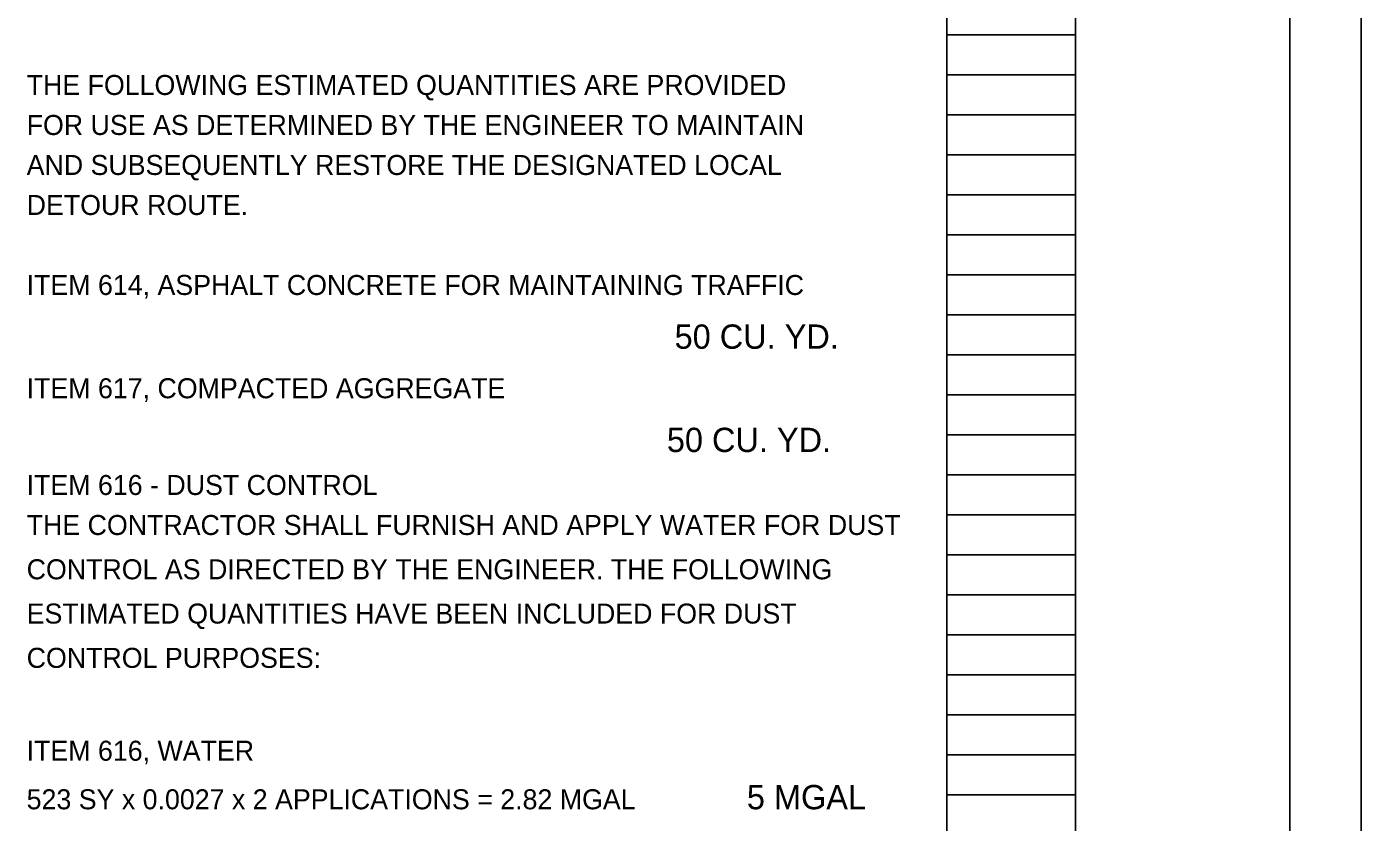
# Model space of a CAD drawing. Extents: x -59.3 to 34, y -1.2 to 22.
# Drawn here: x 24.66 to 34, y 5.55 to 11.12 of the extents above; entities that cross this region are included whole.
import ezdxf

# ---------------------------------------------------------------- set-up
doc = ezdxf.new("R2010")
doc.units = 0
for name, color, linetype in [('RD_P_Text', 7, 'Continuous'), ('SH_Border', 7, 'Continuous'), ('SH_Cut_Line', 7, 'Continuous'), ('SH_Data', 7, 'Continuous')]:
    doc.layers.add(name, color=color, linetype=linetype)

msp = doc.modelspace()

# ---------------------------------------------------------------- linework, layer by layer
at = {"layer": 'RD_P_Text'}
for p, q in [((31.1, 0.98), (31.1, 21.14)), ((32, 0.98), (32, 21.14)), ((31.1, 11.06), (32, 11.06)), ((31.1, 10.78), (32, 10.78)), ((31.1, 10.5), (32, 10.5)), ((31.1, 10.22), (32, 10.22)), ((31.1, 9.94), (32, 9.94)), ((31.1, 9.66), (32, 9.66)), ((31.1, 9.38), (32, 9.38)), ((31.1, 9.1), (32, 9.1)), ((31.1, 8.82), (32, 8.82)), ((31.1, 8.54), (32, 8.54)), ((31.1, 8.26), (32, 8.26)), ((31.1, 7.98), (32, 7.98)), ((31.1, 7.7), (32, 7.7)), ((31.1, 7.42), (32, 7.42)), ((31.1, 7.14), (32, 7.14)), ((31.1, 6.86), (32, 6.86)), ((31.1, 6.58), (32, 6.58)), ((31.1, 6.3), (32, 6.3)), ((31.1, 6.02), (32, 6.02)), ((31.1, 5.74), (32, 5.74))]:
    msp.add_line(p, q, dxfattribs=at)
at = {"layer": 'SH_Border'}
msp.add_line((32, 0.5), (32, 21.5), dxfattribs=at)
msp.add_lwpolyline([(1.5, 21.5), (33.5, 21.5), (33.5, 0.5), (1.5, 0.5)], close=True, dxfattribs=at)
at = {"layer": 'SH_Cut_Line'}
msp.add_lwpolyline([(0, 0), (34, 0), (34, 22), (0, 22)], close=True, dxfattribs=at)

# ---------------------------------------------------------------- texts
at = {"layer": 'SH_Data'}
for s, height, p in [('THE FOLLOWING ESTIMATED QUANTITIES ARE PROVIDED ', 0.14, (24.66, 10.64)), ('FOR USE AS DETERMINED BY THE ENGINEER TO MAINTAIN ', 0.14, (24.66, 10.36)), ('AND SUBSEQUENTLY RESTORE THE DESIGNATED LOCAL ', 0.14, (24.66, 10.08)), ('DETOUR ROUTE.', 0.14, (24.66, 9.8)), ('ITEM 614, ASPHALT CONCRETE FOR MAINTAINING TRAFFIC', 0.14, (24.66, 9.24)), ('50 CU. YD.', 0.17, (29.1943, 8.8636)), ('ITEM 617, COMPACTED AGGREGATE ', 0.14, (24.66, 8.5171)), ('50 CU. YD.', 0.17, (29.14, 8.1407)), ('ITEM 616 - DUST CONTROL', 0.14, (24.66, 7.84)), ('THE CONTRACTOR SHALL FURNISH AND APPLY WATER FOR DUST ', 0.14, (24.66, 7.56)), ('CONTROL AS DIRECTED BY THE ENGINEER. THE FOLLOWING ', 0.14, (24.66, 7.25)), ('ESTIMATED QUANTITIES HAVE BEEN INCLUDED FOR DUST ', 0.14, (24.66, 6.94)), ('CONTROL PURPOSES:', 0.14, (24.66, 6.63)), ('ITEM 616, WATER ', 0.14, (24.66, 5.98)), ('5 MGAL', 0.17, (29.7, 5.64)), ('523 SY x 0.0027 x 2 APPLICATIONS = 2.82 MGAL', 0.14, (24.66, 5.64))]:
    msp.add_text(s, height=height, dxfattribs=at).set_placement(p)

doc.saveas('drawing.dxf')
